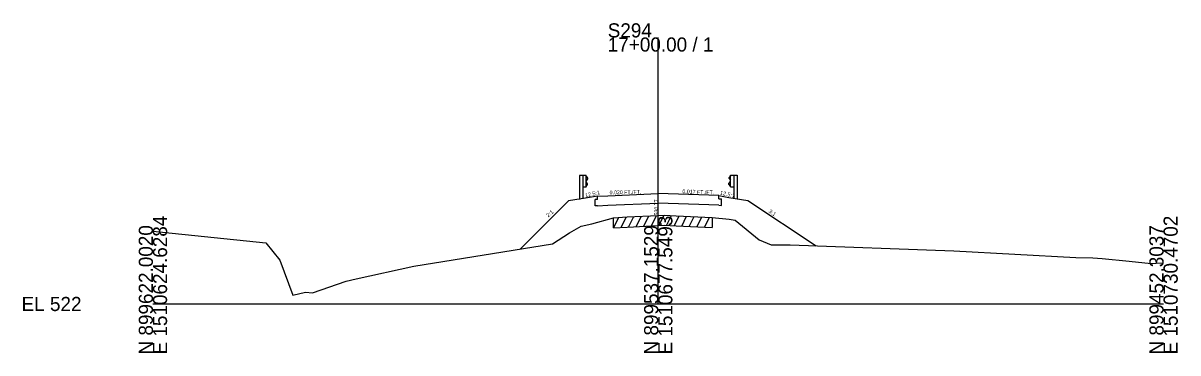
# Model space of a CAD drawing. Extents: x 974 to 2203, y -10 to 19041.
# Drawn here: x 974.3 to 1202.8, y 13990.3 to 14055.6 of the extents above; entities that cross this region are included whole.
import ezdxf

# ---------------------------------------------------------------- set-up
doc = ezdxf.new("R2010")
doc.units = 0
for name, color, linetype in [('RD_GPK_XS_Cell', 7, 'Continuous'), ('RD_XS_Base', 7, 'Continuous'), ('RD_XS_EarthShd', 7, 'Continuous'), ('RD_XS_ExGround', 7, 'Continuous'), ('RD_XS_ExPaveRet', 7, 'Continuous'), ('RD_XS_GR', 7, 'Continuous'), ('RD_XS_Pave', 7, 'Continuous'), ('RD_XS_TX_Elev_EX', 7, 'Continuous'), ('RD_XS_TX_Slope', 7, 'Continuous')]:
    doc.layers.add(name, color=color, linetype=linetype)

msp = doc.modelspace()

# ---------------------------------------------------------------- linework, layer by layer
at = {"layer": 'RD_GPK_XS_Cell'}
for p, q in [((1100, 14000), (1100, 14052.78)), ((1000, 14000), (1100, 14000)), ((1100, 14000), (1200, 14000))]:
    msp.add_line(p, q, dxfattribs=at)
at = {"layer": 'RD_XS_Base'}
for p, q in [((1088, 14020.72), (1087.5, 14020.7)), ((1087.5, 14019.43), (1087.5, 14020.7)), ((1088, 14020.72), (1088, 14021.36)), ((1112.01, 14020.81), (1112, 14021.45)), ((1112.01, 14020.81), (1112.51, 14020.79)), ((1112.52, 14019.52), (1112.51, 14020.79)), ((1088, 14019.45), (1087.5, 14019.43)), ((1088, 14019.45), (1090, 14019.54)), ((1090, 14019.54), (1100.01, 14019.95)), ((1110.02, 14019.61), (1100.01, 14019.95)), ((1112.02, 14019.54), (1110.02, 14019.61)), ((1112.02, 14019.54), (1112.52, 14019.52))]:
    msp.add_line(p, q, dxfattribs=at)
at = {"layer": 'RD_XS_EarthShd'}
for p, q in [((1086, 14021.03), (1082.25, 14020.4)), ((1088, 14021.36), (1086, 14021.03)), ((1112, 14021.45), (1114, 14021.11)), ((1114, 14021.11), (1117.75, 14020.49)), ((1117.75, 14020.49), (1131.24, 14011.5)), ((1072.77, 14010.93), (1082.25, 14020.4))]:
    msp.add_line(p, q, dxfattribs=at)
at = {"layer": 'RD_XS_ExGround'}
msp.add_lwpolyline([(1000, 14014.45), (1022.32, 14012.11), (1025.09, 14008.66), (1027.71, 14001.73), (1030.18, 14002.31), (1031.57, 14002.21), (1038.26, 14004.53), (1040.24, 14004.97), (1051.64, 14007.51), (1079.05, 14011.94), (1082.47, 14014.07), (1084.72, 14015.38), (1086.84, 14015.84), (1091.14, 14017.09), (1093.84, 14017.23), (1100, 14017.54), (1101.17, 14017.59), (1103.52, 14017.45), (1110.64, 14017.13), (1114.03, 14016.78), (1115.22, 14016.6), (1120, 14012.71), (1122.34, 14011.7), (1126.11, 14011.68), (1158.48, 14010.53), (1182.64, 14009.22), (1186.02, 14009.12), (1187.88, 14009.02), (1193.19, 14008.48), (1197.55, 14008.03), (1198.52, 14008.1), (1200, 14008.14)], dxfattribs=at)
at = {"layer": 'RD_XS_ExPaveRet'}
for p, q in [((1091.14, 14015.09), (1092.17, 14017.14)), ((1091.14, 14015.09), (1091.14, 14017.09)), ((1092.64, 14015.17), (1093.67, 14017.22)), ((1094.14, 14015.24), (1095.17, 14017.29)), ((1095.64, 14015.32), (1096.67, 14017.37)), ((1097.14, 14015.39), (1098.17, 14017.44)), ((1098.64, 14015.47), (1099.67, 14017.52)), ((1100.14, 14015.54), (1101.17, 14017.59)), ((1101.64, 14015.57), (1102.61, 14017.51)), ((1103.14, 14015.47), (1104.12, 14017.42)), ((1104.64, 14015.4), (1105.62, 14017.36)), ((1106.14, 14015.33), (1107.12, 14017.29)), ((1107.64, 14015.26), (1108.62, 14017.22)), ((1109.14, 14015.2), (1110.12, 14017.15)), ((1110.64, 14017.13), (1110.64, 14015.13)), ((1091.14, 14015.09), (1093.84, 14015.23)), ((1093.84, 14015.23), (1100, 14015.54)), ((1100, 14015.54), (1101.17, 14015.59)), ((1101.17, 14015.59), (1103.52, 14015.45)), ((1103.52, 14015.45), (1110.64, 14015.13))]:
    msp.add_line(p, q, dxfattribs=at)
at = {"layer": 'RD_XS_GR'}
for p, q in [((1084.4, 14025.44), (1084.4, 14020.68)), ((1085.06, 14025.44), (1084.4, 14025.44)), ((1085.06, 14025.44), (1085.06, 14020.79)), ((1085.73, 14025.44), (1085.06, 14025.44)), ((1085.73, 14023.11), (1085.73, 14025.44)), ((1085.73, 14025.3), (1086, 14024.9)), ((1114.27, 14025.39), (1114, 14024.99)), ((1114.27, 14023.2), (1114.27, 14025.53)), ((1114.27, 14025.53), (1114.94, 14025.53)), ((1114.94, 14025.53), (1114.94, 14020.88)), ((1114.94, 14025.53), (1115.61, 14025.53)), ((1115.61, 14025.53), (1115.61, 14020.76)), ((1085.73, 14023.11), (1085.06, 14023.11)), ((1086, 14024.8), (1085.73, 14024.4)), ((1086, 14023.76), (1085.73, 14024.16)), ((1085.73, 14023.26), (1086, 14023.66)), ((1086, 14024.9), (1086, 14024.8)), ((1086, 14023.66), (1086, 14023.76)), ((1114, 14024.99), (1114, 14024.89)), ((1114, 14024.89), (1114.27, 14024.49)), ((1114, 14023.84), (1114.27, 14024.24)), ((1114, 14023.74), (1114, 14023.84)), ((1114.27, 14023.34), (1114, 14023.74)), ((1114.27, 14023.2), (1114.94, 14023.2))]:
    msp.add_line(p, q, dxfattribs=at)
at = {"layer": 'RD_XS_Pave'}
for p, q in [((1088, 14021.36), (1090, 14021.44)), ((1090, 14021.44), (1100, 14021.86)), ((1110, 14021.52), (1100, 14021.86)), ((1112, 14021.45), (1110, 14021.52))]:
    msp.add_line(p, q, dxfattribs=at)

# ---------------------------------------------------------------- texts
at = {"layer": 'RD_GPK_XS_Cell'}
for s, p in [('S294', (1090, 14052.78)), ('17+00.00 / 1', (1090, 14049.98)), ('EL 522', (974, 13998.6))]:
    msp.add_text(s, height=2.8, dxfattribs=at).set_placement(p)
for s, p in [('E 1510624.6284', (1002.8, 13990)), ('E 1510677.5493', (1102.8, 13990)), ('E 1510730.4702', (1202.8, 13990)), ('N 899622.0020', (1000, 13990)), ('N 899537.1529', (1100, 13990)), ('N 899452.3037', (1200, 13990))]:
    msp.add_text(s, height=2.8, rotation=90, dxfattribs=at).set_placement(p)
at = {"layer": 'RD_XS_TX_Elev_EX'}
msp.add_text('530.77', height=0.75, rotation=90, dxfattribs=at).set_placement((1100, 14017.54))
at = {"layer": 'RD_XS_TX_Slope'}
for s, height, rotation, p in [('12.5:1', 0.778, 12.7511, (1085.61, 14021.1)), ('0.020 FT./FT.', 0.7518, 1.1916, (1090.38, 14021.7)), ('0.017 FT./FT.', 0.7518, 357.9569, (1104.78, 14021.93)), ('12.5:1', 0.778, 347.2489, (1112.17, 14021.69)), ('2:1', 0.778, 40.6589, (1078.23, 14017.12)), ('3:1', 0.778, 324.722, (1121.76, 14018.18))]:
    msp.add_text(s, height=height, rotation=rotation, dxfattribs=at).set_placement(p)

doc.saveas('drawing.dxf')
